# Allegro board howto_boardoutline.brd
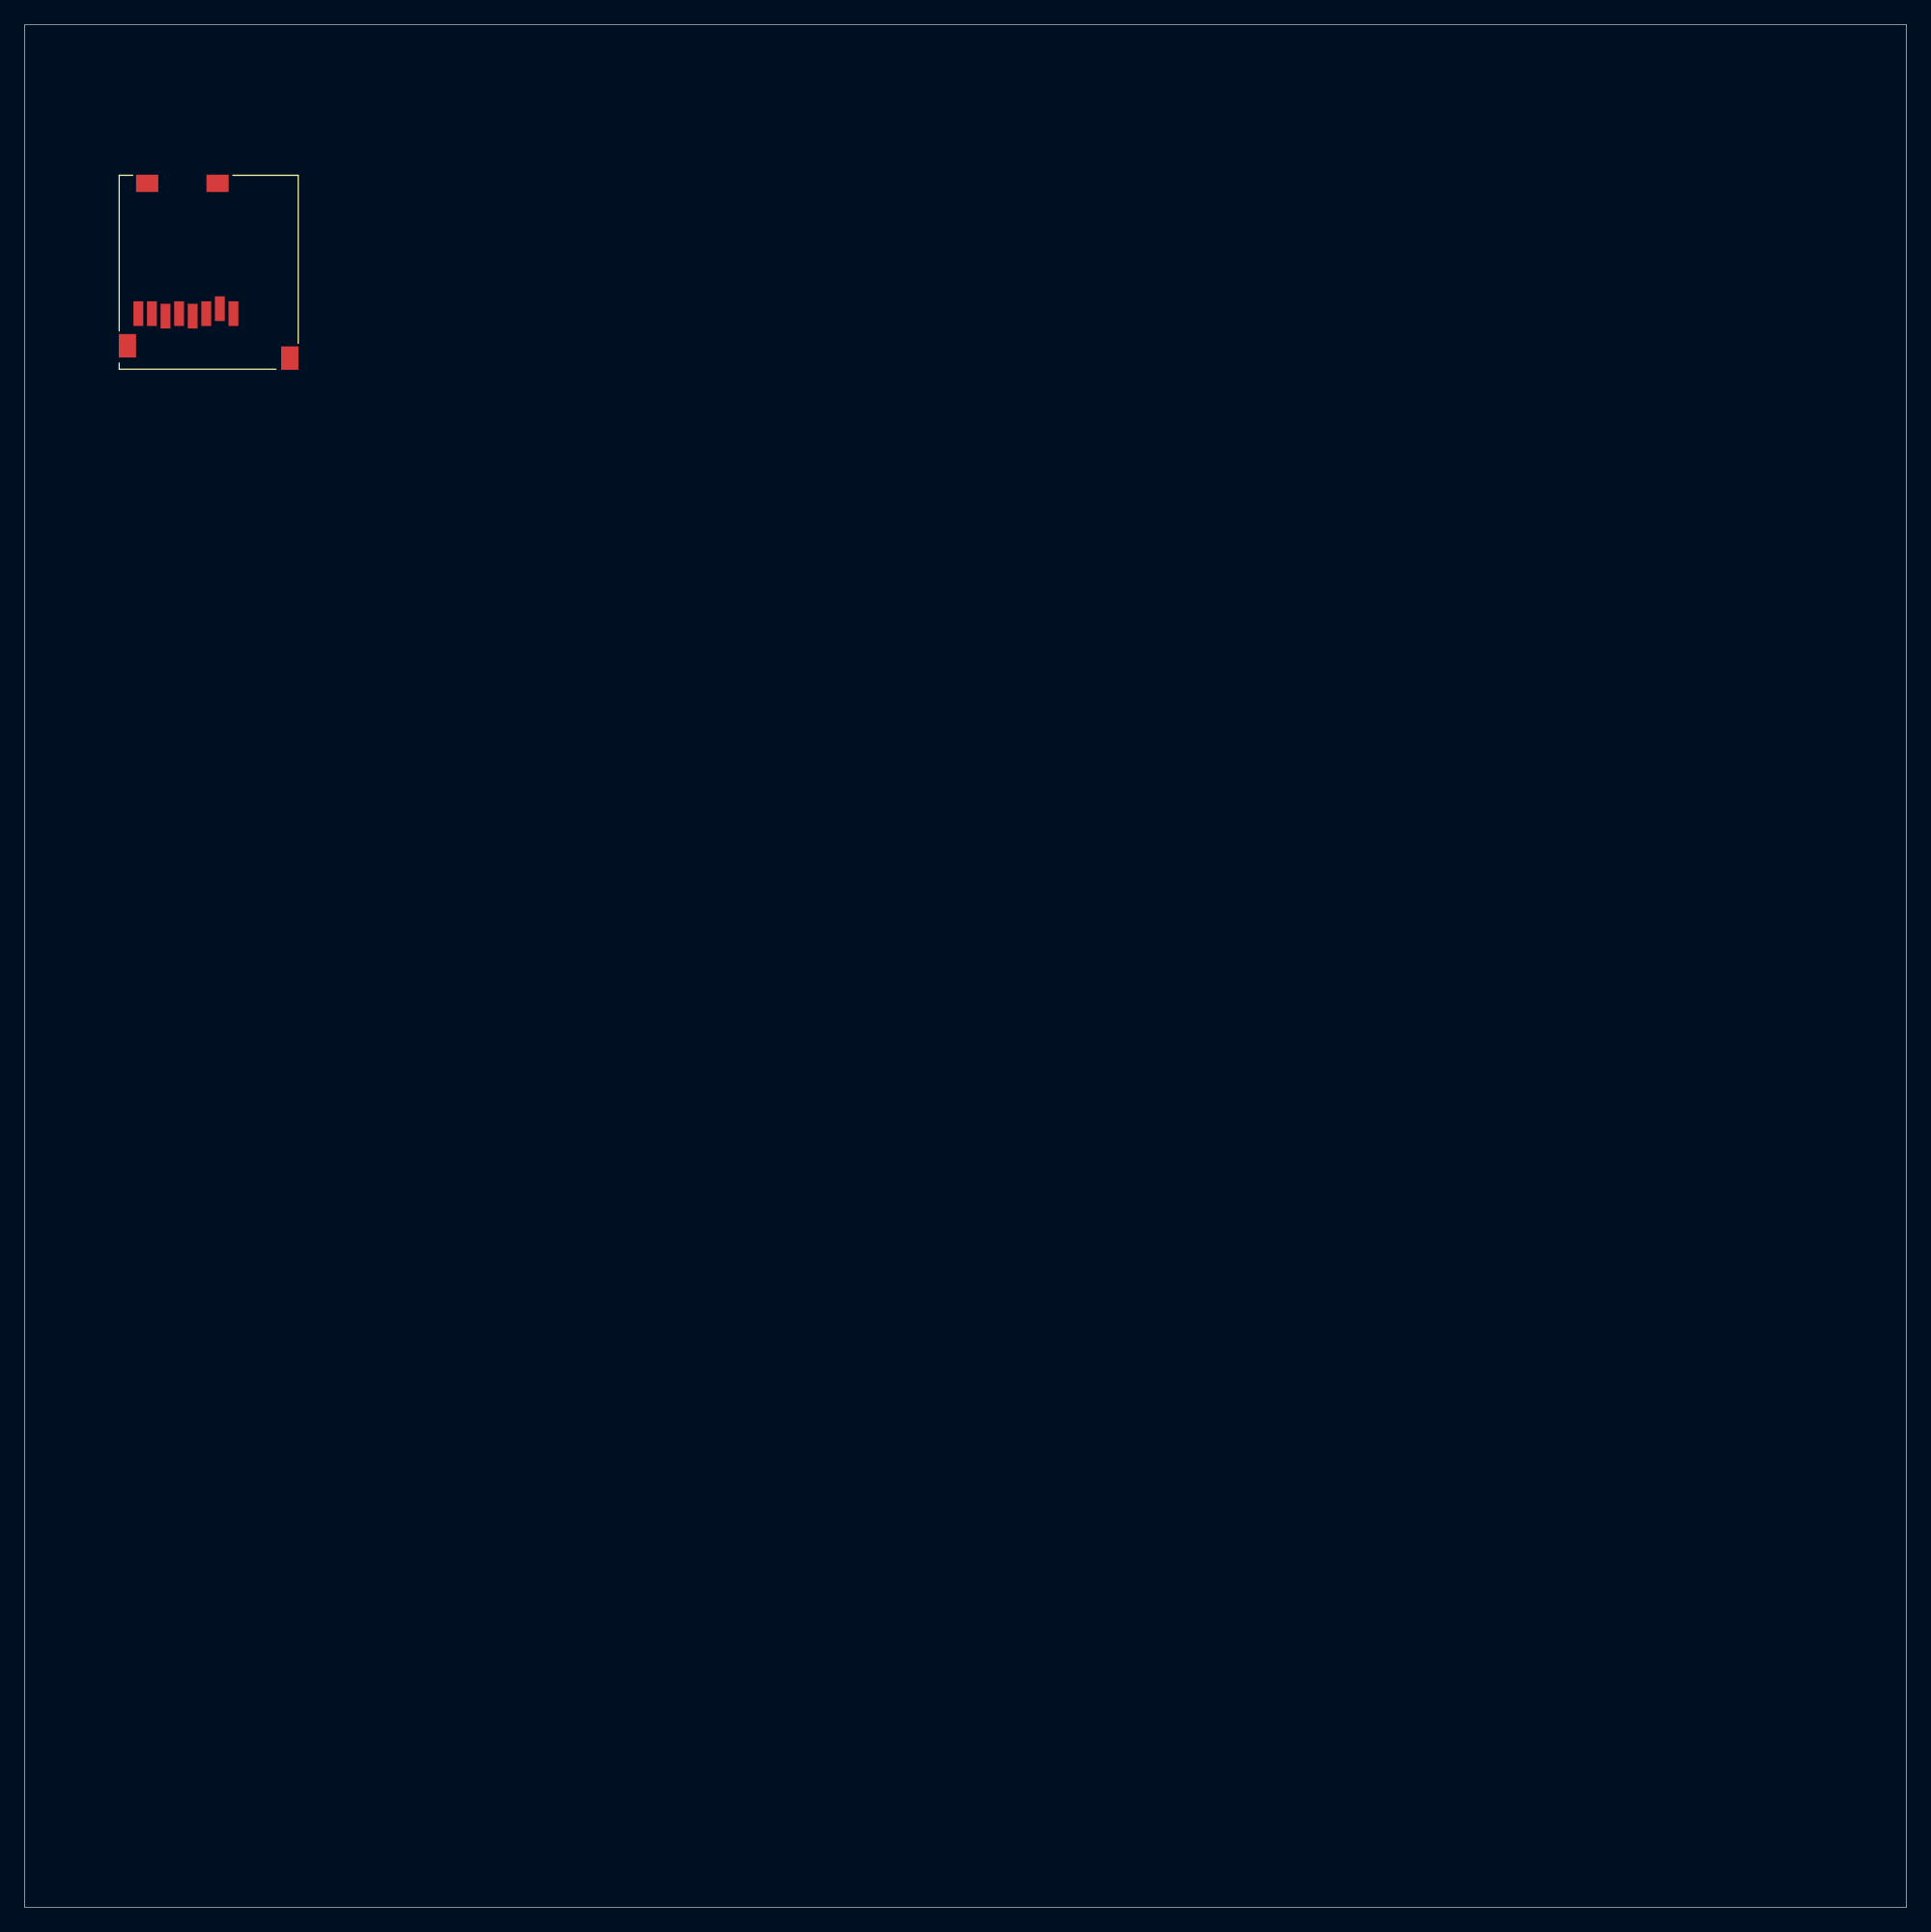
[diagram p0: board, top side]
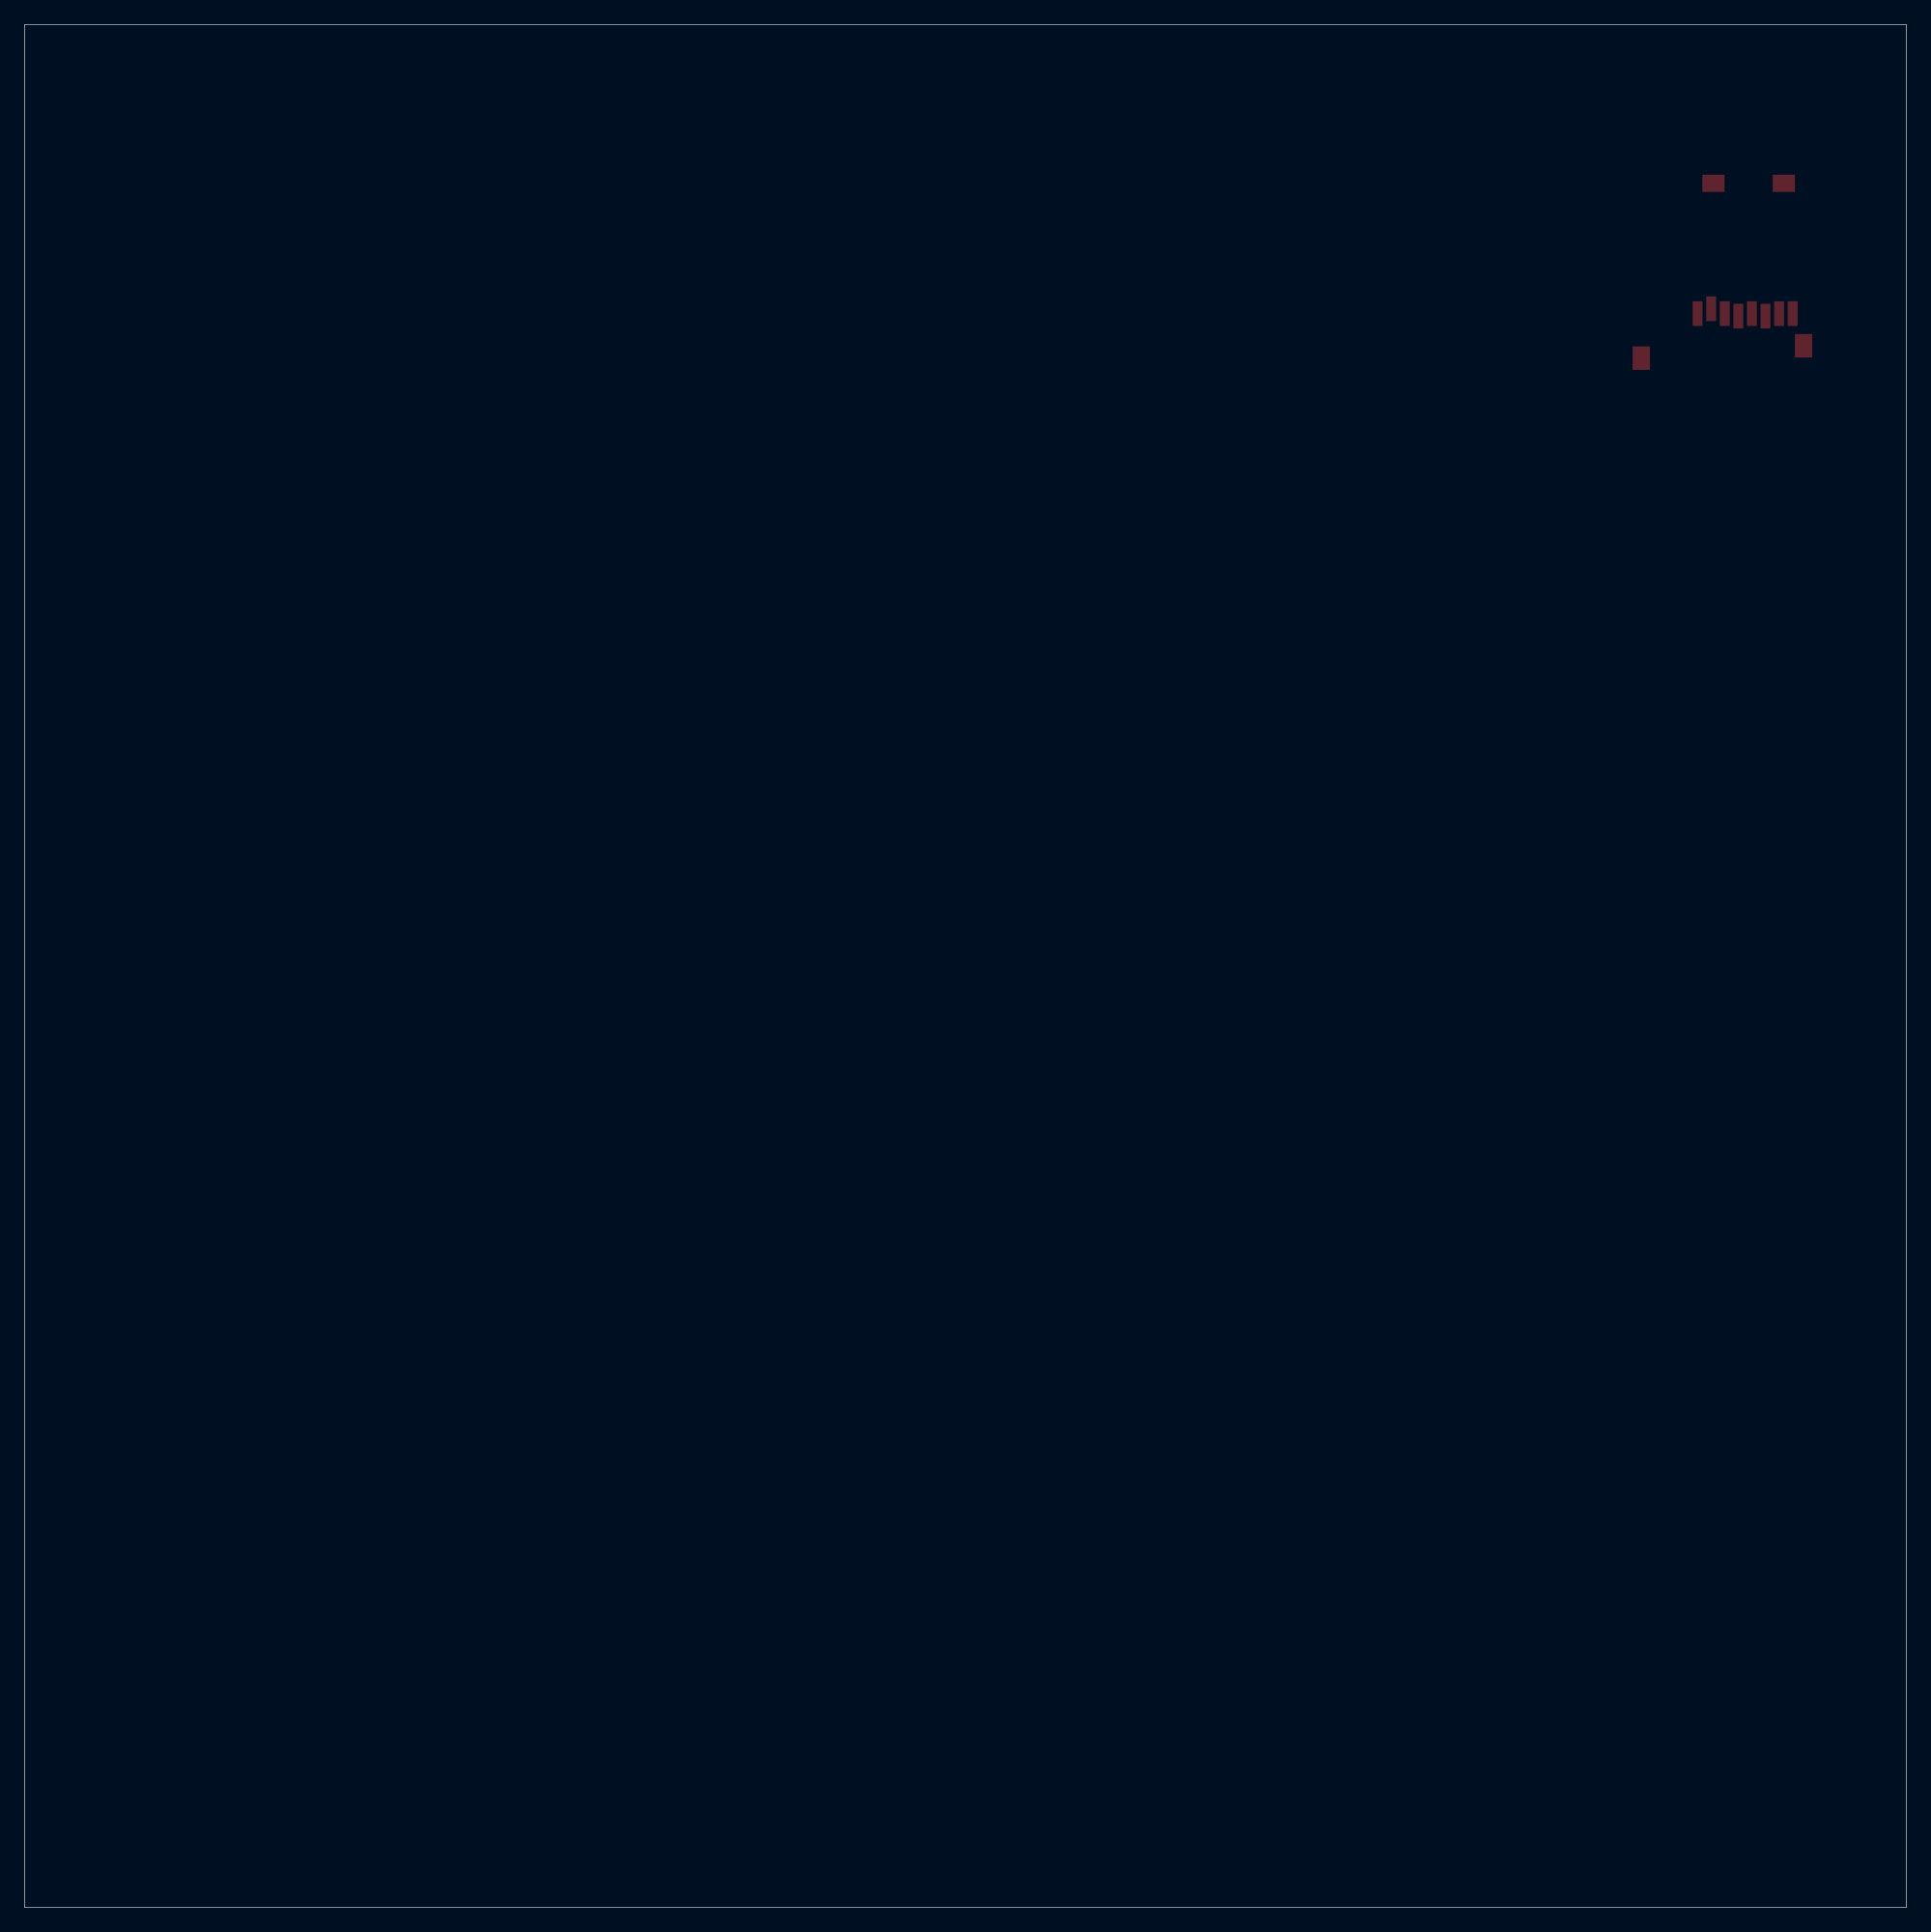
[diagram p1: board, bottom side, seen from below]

Outline 152.4 x 152.4 mm; copper layers: TOP, BOTTOM. Coordinates in mm from the lower left corner of the outline.
Outline path: 0,152.4 152.4,152.4 152.4,0 0,0 0,152.4

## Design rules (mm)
constraint set DEFAULT: min track width 0.127

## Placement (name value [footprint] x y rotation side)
SD2  -  [MEM2061]  13.06 129.01 0 top

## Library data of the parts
SD2 = MEM2061

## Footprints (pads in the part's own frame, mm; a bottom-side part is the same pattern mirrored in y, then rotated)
MEM2061
  rect 0.8x2 smd: 1(3.85,0) 2(2.75,0.4) 3(1.65,0) 4(0.55,-0.2) 5(-0.55,0) 6(-1.65,-0.2) 7(-2.75,0) 8(-3.85,0)
  rect 1.4x1.9 smd: P1(-4.735,-2.6) P2(8.415,-3.6)
  rect 1.8x1.4 smd: SW1(-3.135,10.55) SW2(2.565,10.55)

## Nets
+3V3: SD2.4
GND: SD2.6(VSS) SD2.P1 SD2.P2 SD2.SW2
SD_CARD_DETECT: SD2.SW1
SD_CS: SD2.2
SD_MISO: SD2.7
SD_MOSI: SD2.3
SD_SCK: SD2.5

Pads without a net: SD2 1 8
